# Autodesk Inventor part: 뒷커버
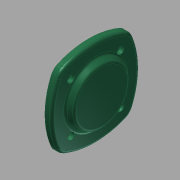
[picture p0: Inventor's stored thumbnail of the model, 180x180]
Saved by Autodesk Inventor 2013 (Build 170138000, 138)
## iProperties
Created: 2015-11
Part Number: 뒷커버
Material: 일반
Document SubType Name: Modeling
Designer: mduedu
Density: 1 g/cm^3
Mass: 120.056 g
Surface Area: 247.582 cm^2
Volume: 120.056 cm^3
Author: mduedu
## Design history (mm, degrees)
sketch "스케치1"
  geometry: L1 (50, 50)-(-50, 50); L2 (-50, 50)-(-50, -50); L3 (-50, -50)-(50, -50); L4 (50, -50)-(50, 50); L5 (0, 50)-(0, -50); L6 (50, 0)-(-50, 0); A1 r 90 centre (-40, 0) between (40.415, -40.415) and (40.415, 40.415); A2 r 90 centre (40, 0) between (-40.415, 40.415) and (-40.415, -40.415); A3 r 90 centre (0, -40) between (40.415, 40.415) and (-40.415, 40.415); A4 r 90 centre (0, 40) between (-40.415, -40.415) and (40.415, -40.415); 2 further points
  constraints: 12 end point, 8 point on circle, 5 midpoint, 4 centre point, 2 horizontal alignment, 2 parallel, 2 perpendicular, 2 symmetric about line, 2 tangent, 2 vertical alignment, 1 equal radius, 1 horizontal, 2 other
  dimensions: "d0" = 100 distance of L3.end L1.start; "d2" = 90 radius of A1
extrude "돌출1" new body sketch "스케치1" distance "d3" = 8; taper "d4" = 0 deg
sketch "스케치2"
  geometry: C1 r 35 at (0, 0); 1 further point
  constraints: 1 centre point, 1 coincident
  dimensions: "d5" = 70 diameter of C1
extrude "돌출2" join sketch "스케치2" distance "d6" = 7; taper "d7" = -30 deg
sketch "스케치3"
  geometry: L1 (0, 0)-(0, 40); L2 (0, 0)-(-28.284, 28.284); A1 r 40 centre (0, 0) between (0, 40) and (-28.284, 28.284); 2 further points
  constraints: 4 end point, 2 coincident, 2 point on circle, 1 centre point, 1 vertical
  dimensions: "d8" = 80 diameter of A1; "d9" = 45 deg angle of L1 L2
hole "구멍1" sketch "스케치3" at (-28.284, 28.284) diameter "d11" = 4.5; stored, may be unused: countersink angle "d15" = 90 deg, drill point angle "d17" = 118 deg; dims "d12" = 6, "d13" = 8, "d14" = 4.4, "d16" = 8
sketch "스케치4"
  geometry: C1 r 35 at (0, 0); 1 further point
  constraints: 1 centre point, 1 coincident
  dimensions: "d21" = 70 diameter of C1
extrude "돌출3" join sketch "스케치4" distance "d23" = 12; taper "d24" = 0 deg
hole "구멍2" diameter "d27" = 30; stored, may be unused: countersink angle "d31" = 90 deg, drill point angle "d33" = 0 deg; dims "d25" = 10, "d26" = 10, "d28" = 6, "d29" = 40, "d30" = 12, "d32" = 15
fillet "모깎기2" dims "d35" = 15
fillet "모깎기3" dims "d36" = 3
fillet "모깎기4" dims "d37" = 3
fillet "모깎기5" dims "d38" = 0.3
chamfer "모따기1" distance "d39" = 1; stored, may be unused: second distance "d40" = 2, angle "d41" = 45 deg
node "솔리드1"
pattern_circular "원형 패턴1" dims angle "d19" = 360 deg
